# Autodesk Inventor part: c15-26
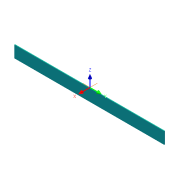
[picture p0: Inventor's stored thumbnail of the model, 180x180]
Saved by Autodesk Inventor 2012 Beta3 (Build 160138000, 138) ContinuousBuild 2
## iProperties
Created: 2011-02
Part Number: c15-26
Material: Default
Document SubType Name: Modeling
Designer: Beta-8540w
Density: 1 g/cm^3
Author: Beta-8540w
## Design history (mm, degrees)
sketch "Sketch1"
  geometry: L1 (-100.6, 7.937)-(100.6, 7.937); L2 (100.6, 7.937)-(100.6, -7.938); L3 (100.6, -7.938)-(-100.6, -7.938); L4 (-100.6, -7.938)-(-100.6, 7.937); 3 further points
  constraints: 8 end point, 2 midpoint, 2 parallel, 1 horizontal, 1 horizontal alignment, 1 perpendicular, 1 vertical alignment
  dimensions: "length" = 201.2 distance of L1.start L1.end; "d1" = 15.875 distance of L3.end L1.start
extrude "Extrusion1" new body sketch "Sketch1" taper "d3" = 0 deg; distance "thickness" = 1
body "Solid1"
other parameters: "d4" = 0, "d5" = 0, "d6" = 0, "d7" = 0, "d8" = 0, "d9" = 0
